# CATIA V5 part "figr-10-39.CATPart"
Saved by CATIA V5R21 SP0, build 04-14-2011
Part number: Part3
Bounding box of the stored display mesh (mm): x -76.186 to 89.68, y -206 to 106, z -21.666 to 136.547
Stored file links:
  D:\CATIA V5R21 E-RESOURCES\CATIA-V5R21\catia-v5r21-prt\c10-catia-v5r20-prt\c10-catia-v5r21-figr-10-39.CATPart
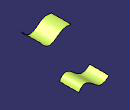
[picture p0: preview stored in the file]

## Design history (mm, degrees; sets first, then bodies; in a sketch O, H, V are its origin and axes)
Set1
  Plane1: type Offset, RefPlane zx-plane, Offset 100, reversed
  Sketch1 on Plane1, origin (0, -100, 0), H (-1, 0, 0), V (0, 0, 1)
    spline S1 through (-89.6797, 128.7958) (-21.8257, 98.6681) (14.6145, 123.4397) (76.1857, 133.4823)
  Extrude1: Element1 Sketch2, Lim1 106, Lim2 0, Direction zx-plane
  Extrude2: Element1 Sketch1, Lim1 106, Lim2 0, Direction Plane1
Body1 (main body)
  Sketch2 on zx-plane, origin (0, 0, 0), H (-1, 0, 0), V (0, 0, 1)
    spline S1 through (-88.2413, 0) (-57.9275, 26.3209) (-11.5211, 3.1904) (32.6399, -21.5353) (74.1811, 0)
    point P1 (-88.2413, 0)
    point P2 (74.1811, 0)
    coincidence: P1 H, P2 H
